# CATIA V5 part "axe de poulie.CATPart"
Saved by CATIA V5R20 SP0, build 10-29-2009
Part number: 8
Bounding box of the stored display mesh (mm): x -6 to 6, y -5.85 to 5.85, z 0 to 20
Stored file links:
  C:\Users\halimelbaba\Documents\cmv\projet\axe de poulie.CATPart
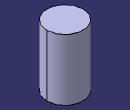
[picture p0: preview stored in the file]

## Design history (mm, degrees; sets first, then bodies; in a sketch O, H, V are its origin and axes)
Body1 (main body)
  Sketch1 on xy-plane, origin (0, 0, 0), H (1, 0, 0), V (0, 1, 0)
    circle A1 centre (0, 0) radius 6
    radius A1 = 6
  Pad1: profile Sketch1, direction (0, 0, 1), length 20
